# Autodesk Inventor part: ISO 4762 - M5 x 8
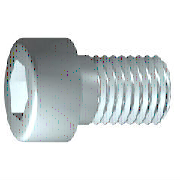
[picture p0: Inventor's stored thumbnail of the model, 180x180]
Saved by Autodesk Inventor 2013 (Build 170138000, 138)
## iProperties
Created: 2012-02
Part Number: ISO 4762 - M5 x 8
Material: Edelstahl, 440C
Description: Innensechskantschraube
Document SubType Name: Modeling
Standard: ISO 4762
Designer: Dan
Standard Revision: 1998
Standards Organization: DIN
Language: de-DE
Size Designation: M5 x 8
Categories: <MemberInstance><Categories><Category DisplayName="Verbindungselemente" InternalName="e4da775c-781d-43d5-af7c-5136215cf5a6" Mnemonic="FSTN"><Category DisplayNam
Density: 7.75 g/cm^3
IsCustomPart: 0
Author: Dan
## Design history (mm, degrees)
sketch "Skizze1"
  geometry: L1 (-1.167, 0)-(8, 0); L2 (8, 0)-(8, 2.5); L3 (8, 2.5)-(2, 2.5); L4 (2, 2.5)-(1.509, 2.5); L5 (1.509, 2.5)-(0, 2.5); L6 (0, 2.5)-(0, 4.25); L7 (0, 4.25)-(-5, 4.25); L8 (-5, 4.25)-(-5, 2.309); L9 (-5, 2.309)-(-2.5, 2.309); L10 (-2.5, 2.309)-(-1.167, 0); L11 (-7.6, 0)-(10.6, 0) reference; L12 (0, -0.85)-(0, 5.1) reference; L13 (2, 2.5)-(0, 2.5)
  constraints: 22 end point, 6 parallel, 2 collinear, 2 perpendicular, 1 horizontal, 1 point on line
  dimensions: "d1" = 6 distance from line of L3.end L2 (= GEL); "d2" = 0.49086 distance of L4.end L3.end (computed from GAL); "d3" = 5 distance between parallel lines of L8 L6 (= KOH); "d4" = 2.5 distance of L8.end L9.end (= INTI); "d5" = 60 deg angle of L10 L1; "d6" = 5 diameter of L3 L1 (= GD); "d7" = 5 diameter of L5 L1 (= BDM); "d8" = 4.6188 diameter of L9 L1 (= 1.1547 x SW); "d9" = 8.5 diameter of L7 L1 (= KOD); "d26" = 8 distance between parallel lines of L12 L2 (= NLG)
revolve "Körper" sketch "Skizze1" stored, may be unused: angle "d10" = 90 deg
sketch "Skizze2"
  geometry: L1 (0, -5.95)-(0, 5.95) reference; L2 (-5.95, 0)-(5.95, 0) reference; L3 (2.309, 0)-(1.155, -2); L4 (1.155, -2)-(-1.155, -2); L5 (-1.155, -2)-(-2.309, 0); L6 (-2.309, 0)-(-1.155, 2); L7 (-1.155, 2)-(1.155, 2); L8 (1.155, 2)-(2.309, 0); 2 further points
  constraints: 12 end point, 1 coincident, 1 horizontal alignment, 1 point on line, 12 other
extrude "Loch" join sketch "Skizze2" stored distance "d11" = 10; taper "d12" = 0 deg
workplane "Work Plane1"
fillet "Fillet2" dims "d30" = 0.1 (= R)
body "Solid1"
fillet "Rundung1" dims "d17" = 0.5 (= RR)
feature "Gewinde" dims "d13" = 6 (= GEL), "d14" = 0
chamfer "Fase1" distance "d15" = 0.49076 (= -0.5 x SPD + 0.5 x GD); stored, may be unused: second distance "d16" = 0.49076 (= GUL), angle "d27" = 45 deg
other parameters: "GD" = 5 [user parameter; used in 2 equation terms], "NLG" = 8 [user parameter; used in 1 equation term], "GEL" = 6 [user parameter; used in 2 equation terms], "KOD" = 8.5 [user parameter; used in 1 equation term], "KOH" = 5 [user parameter; used in 1 equation term], "INTI" = 2.5 [user parameter; used in 1 equation term], "GAL" = 0.49076 (= 0.61345 x PTC) [user parameter; used in 1 equation term], "GUL" = 0.49076 (= 0.61345 x PTC) [user parameter; used in 1 equation term], "BDM" = 5 (= NND) [user parameter; used in 1 equation term], "SW" = 4 [user parameter; used in 2 equation terms], "RR" = 0.5 [user parameter; used in 1 equation term], "SPD" = 4.01848 (= NND - 1.2269 x PTC) [user parameter; used in 1 equation term], "d19" = 0, "d28" = 0, "d29" = 0, "R" = 0.1 [user parameter; used in 1 equation term], "TOA" = 30 deg [user parameter], "GD1" = 4.01848 (= THREADDIA - 1.2269 x PTC) [user parameter], "THREADDIA" = 5 [user parameter; used in 1 equation term], "FAWI" = 45 deg [user parameter], "TPU" = 12.5 (computed from PTC) [user parameter], "PTC" = 0.8 [user parameter; used in 5 equation terms], "NND" = 5 [user parameter; used in 2 equation terms], "E0" = 4.62 (= 1.155 x SW) [user parameter]
